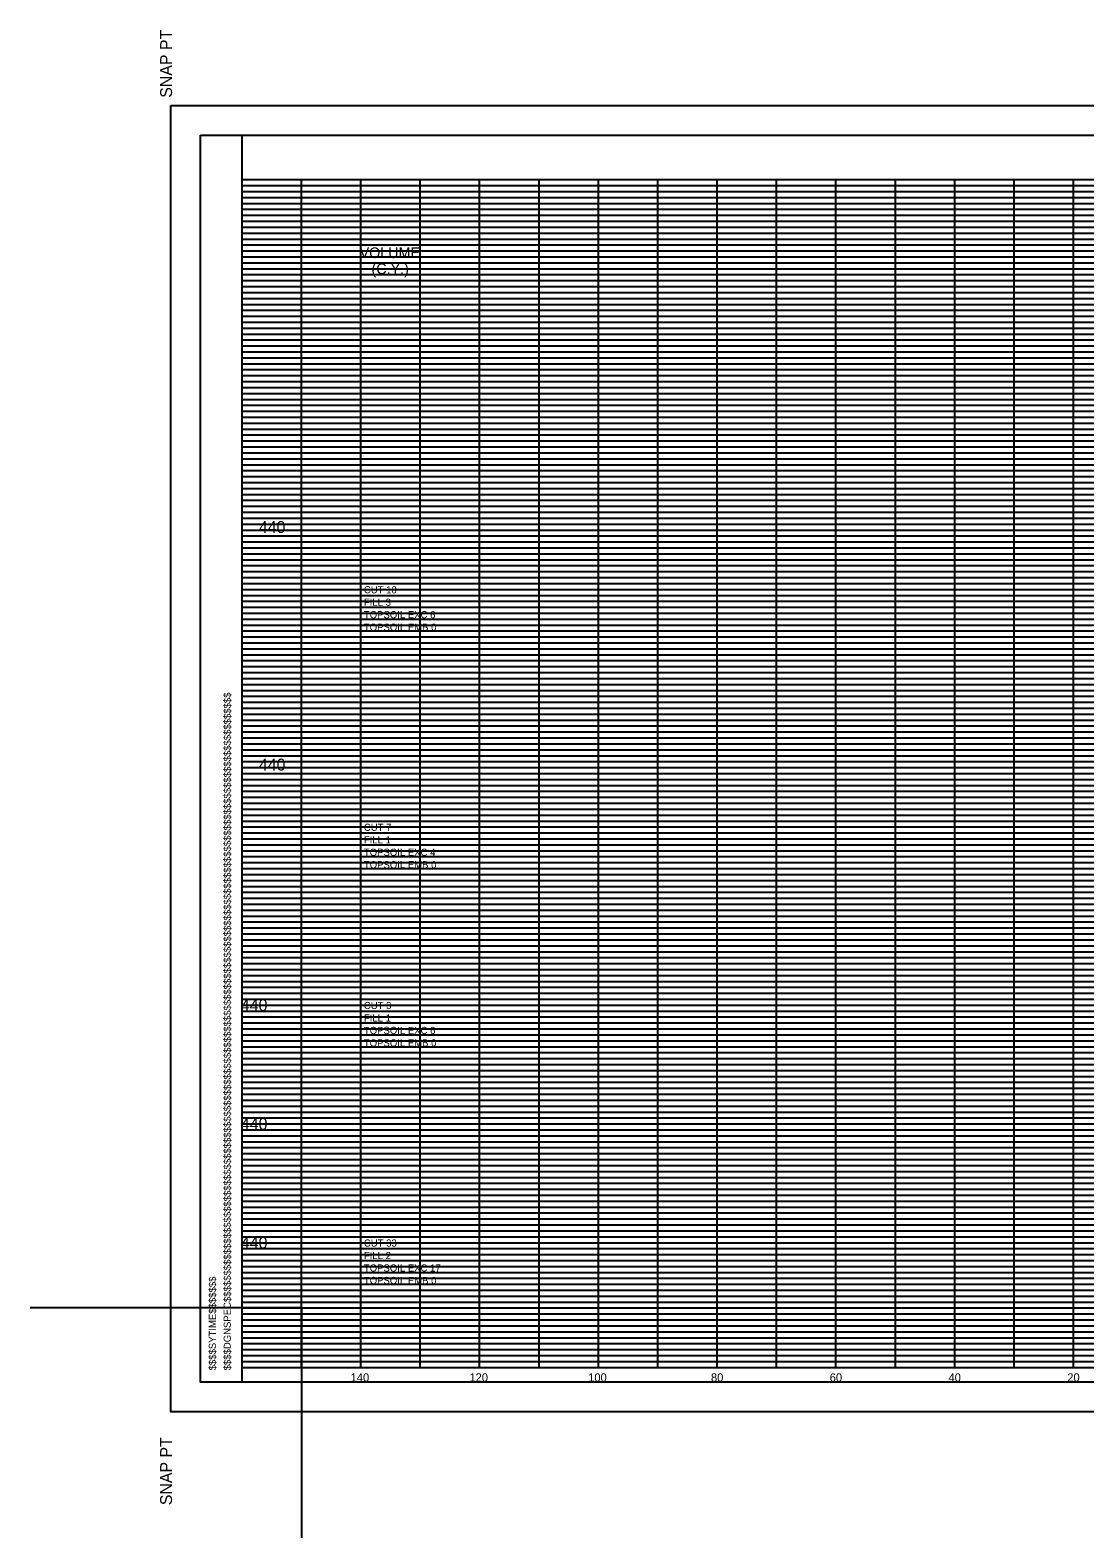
# Model space of a CAD drawing. Extents: x 37 to 1710, y 707 to 2305.
# Drawn here: x 1344.3 to 1521.9, y 1511.3 to 1765.2 of the extents above; entities that cross this region are included whole.
import ezdxf

# ---------------------------------------------------------------- set-up
doc = ezdxf.new("R2010")
doc.units = 0
for name, color, linetype in [('DESIGN - SCRATCH - User 1', 7, 'Continuous'), ('DESIGN - SHEET - Corner Text', 7, 'Continuous'), ('DESIGN - SHEET - Light Grid', 7, 'Continuous'), ('DESIGN - SHEET - Linework', 7, 'Continuous'), ('DESIGN - SHEET - Plot Shape', 7, 'Continuous'), ('DESIGN - TYPICAL - Text', 7, 'Continuous')]:
    doc.layers.add(name, color=color, linetype=linetype)

msp = doc.modelspace()

# ---------------------------------------------------------------- linework, layer by layer
at = {"layer": 'DESIGN - SCRATCH - User 1'}
for p, q in [((1390, 1550), (1344.31, 1550)), ((1390, 1550), (1390, 1511.3)), ((1380, 1540), (1380, 1540))]:
    msp.add_line(p, q, dxfattribs=at)
at = {"layer": 'DESIGN - SHEET - Light Grid'}
for p, q in [((1380, 1739), (1700, 1739)), ((1380, 1738), (1700, 1738)), ((1380, 1737), (1700, 1737)), ((1380, 1736), (1700, 1736)), ((1380, 1735), (1700, 1735)), ((1380, 1734), (1700, 1734)), ((1380, 1733), (1700, 1733)), ((1380, 1732), (1700, 1732)), ((1380, 1731), (1700, 1731)), ((1380, 1729), (1700, 1729)), ((1380, 1728), (1700, 1728)), ((1380, 1727), (1700, 1727)), ((1380, 1726), (1700, 1726)), ((1380, 1725), (1700, 1725)), ((1380, 1724), (1700, 1724)), ((1380, 1723), (1700, 1723)), ((1380, 1722), (1700, 1722)), ((1380, 1721), (1700, 1721)), ((1380, 1719), (1700, 1719)), ((1380, 1718), (1700, 1718)), ((1380, 1717), (1700, 1717)), ((1380, 1716), (1700, 1716)), ((1380, 1715), (1700, 1715)), ((1380, 1714), (1700, 1714)), ((1380, 1713), (1700, 1713)), ((1380, 1712), (1700, 1712)), ((1380, 1711), (1700, 1711)), ((1380, 1709), (1700, 1709)), ((1380, 1708), (1700, 1708)), ((1380, 1707), (1700, 1707)), ((1380, 1706), (1700, 1706)), ((1380, 1705), (1700, 1705)), ((1380, 1704), (1700, 1704)), ((1380, 1703), (1700, 1703)), ((1380, 1702), (1700, 1702)), ((1380, 1701), (1700, 1701)), ((1380, 1699), (1700, 1699)), ((1380, 1698), (1700, 1698)), ((1380, 1697), (1700, 1697)), ((1380, 1696), (1700, 1696)), ((1380, 1695), (1700, 1695)), ((1380, 1694), (1700, 1694)), ((1380, 1693), (1700, 1693)), ((1380, 1692), (1700, 1692)), ((1380, 1691), (1700, 1691)), ((1380, 1689), (1700, 1689)), ((1380, 1688), (1700, 1688)), ((1380, 1687), (1700, 1687)), ((1380, 1686), (1700, 1686)), ((1380, 1685), (1700, 1685)), ((1380, 1684), (1700, 1684)), ((1380, 1683), (1700, 1683)), ((1380, 1682), (1700, 1682)), ((1380, 1681), (1700, 1681)), ((1380, 1679), (1700, 1679)), ((1380, 1678), (1700, 1678)), ((1380, 1677), (1700, 1677)), ((1380, 1676), (1700, 1676)), ((1380, 1675), (1700, 1675)), ((1380, 1674), (1700, 1674)), ((1380, 1673), (1700, 1673)), ((1380, 1672), (1700, 1672)), ((1380, 1671), (1700, 1671)), ((1380, 1669), (1700, 1669)), ((1380, 1668), (1700, 1668)), ((1380, 1667), (1700, 1667)), ((1380, 1666), (1700, 1666)), ((1380, 1665), (1700, 1665)), ((1380, 1664), (1700, 1664)), ((1380, 1663), (1700, 1663)), ((1380, 1662), (1700, 1662)), ((1380, 1661), (1700, 1661)), ((1380, 1659), (1700, 1659)), ((1380, 1658), (1700, 1658)), ((1380, 1657), (1700, 1657)), ((1380, 1656), (1700, 1656)), ((1380, 1655), (1700, 1655)), ((1380, 1654), (1700, 1654)), ((1380, 1653), (1700, 1653)), ((1380, 1652), (1700, 1652)), ((1380, 1651), (1700, 1651)), ((1380, 1649), (1700, 1649)), ((1380, 1648), (1700, 1648)), ((1380, 1647), (1700, 1647)), ((1380, 1646), (1700, 1646)), ((1380, 1645), (1700, 1645)), ((1380, 1644), (1700, 1644)), ((1380, 1643), (1700, 1643)), ((1380, 1642), (1700, 1642)), ((1380, 1641), (1700, 1641)), ((1380, 1639), (1700, 1639)), ((1380, 1638), (1700, 1638)), ((1380, 1637), (1700, 1637)), ((1380, 1636), (1700, 1636)), ((1380, 1635), (1700, 1635)), ((1380, 1634), (1700, 1634)), ((1380, 1633), (1700, 1633)), ((1380, 1632), (1700, 1632)), ((1380, 1631), (1700, 1631)), ((1380, 1629), (1700, 1629)), ((1380, 1628), (1700, 1628)), ((1380, 1627), (1700, 1627)), ((1380, 1626), (1700, 1626)), ((1380, 1625), (1700, 1625)), ((1380, 1624), (1700, 1624)), ((1380, 1623), (1700, 1623)), ((1380, 1622), (1700, 1622)), ((1380, 1621), (1700, 1621)), ((1380, 1619), (1700, 1619)), ((1380, 1618), (1700, 1618)), ((1380, 1617), (1700, 1617)), ((1380, 1616), (1700, 1616)), ((1380, 1615), (1700, 1615)), ((1380, 1614), (1700, 1614)), ((1380, 1613), (1700, 1613)), ((1380, 1612), (1700, 1612)), ((1380, 1611), (1700, 1611)), ((1380, 1609), (1700, 1609)), ((1380, 1608), (1700, 1608)), ((1380, 1607), (1700, 1607)), ((1380, 1606), (1700, 1606)), ((1380, 1605), (1700, 1605)), ((1380, 1604), (1700, 1604)), ((1380, 1603), (1700, 1603)), ((1380, 1602), (1700, 1602)), ((1380, 1601), (1700, 1601)), ((1380, 1599), (1700, 1599)), ((1380, 1598), (1700, 1598)), ((1380, 1597), (1700, 1597)), ((1380, 1596), (1700, 1596)), ((1380, 1595), (1700, 1595)), ((1380, 1594), (1700, 1594)), ((1380, 1593), (1700, 1593)), ((1380, 1592), (1700, 1592)), ((1380, 1591), (1700, 1591)), ((1380, 1589), (1700, 1589)), ((1380, 1588), (1700, 1588)), ((1380, 1587), (1700, 1587)), ((1380, 1586), (1700, 1586)), ((1380, 1585), (1700, 1585)), ((1380, 1584), (1700, 1584)), ((1380, 1583), (1700, 1583)), ((1380, 1582), (1700, 1582)), ((1380, 1581), (1700, 1581)), ((1380, 1579), (1700, 1579)), ((1380, 1578), (1700, 1578)), ((1380, 1577), (1700, 1577)), ((1380, 1576), (1700, 1576)), ((1380, 1575), (1700, 1575)), ((1380, 1574), (1700, 1574)), ((1380, 1573), (1700, 1573)), ((1380, 1572), (1700, 1572)), ((1380, 1571), (1700, 1571)), ((1380, 1569), (1700, 1569)), ((1380, 1568), (1700, 1568)), ((1380, 1567), (1700, 1567)), ((1380, 1566), (1700, 1566)), ((1380, 1565), (1700, 1565)), ((1380, 1564), (1700, 1564)), ((1380, 1563), (1700, 1563)), ((1380, 1562), (1700, 1562)), ((1380, 1561), (1700, 1561)), ((1380, 1559), (1700, 1559)), ((1380, 1558), (1700, 1558)), ((1380, 1557), (1700, 1557)), ((1380, 1556), (1700, 1556)), ((1380, 1555), (1700, 1555)), ((1380, 1554), (1700, 1554)), ((1380, 1553), (1700, 1553)), ((1380, 1552), (1700, 1552)), ((1380, 1551), (1700, 1551)), ((1380, 1549), (1700, 1549)), ((1380, 1548), (1700, 1548)), ((1380, 1547), (1700, 1547)), ((1380, 1546), (1700, 1546)), ((1380, 1545), (1700, 1545)), ((1380, 1544), (1700, 1544)), ((1380, 1543), (1700, 1543)), ((1380, 1542), (1700, 1542)), ((1380, 1541), (1700, 1541))]:
    msp.add_line(p, q, dxfattribs=at)
at = {"layer": 'DESIGN - SHEET - Linework'}
for p, q in [((1380, 1740), (1700, 1740)), ((1390, 1540), (1390, 1740)), ((1400, 1540), (1400, 1740)), ((1410, 1540), (1410, 1740)), ((1420, 1540), (1420, 1740)), ((1430, 1540), (1430, 1740)), ((1440, 1540), (1440, 1740)), ((1450, 1540), (1450, 1740)), ((1460, 1540), (1460, 1740)), ((1470, 1540), (1470, 1740)), ((1480, 1540), (1480, 1740)), ((1490, 1540), (1490, 1740)), ((1500, 1540), (1500, 1740)), ((1510, 1540), (1510, 1740)), ((1520, 1540), (1520, 1740)), ((1380, 1730), (1700, 1730)), ((1380, 1720), (1700, 1720)), ((1380, 1710), (1700, 1710)), ((1380, 1700), (1700, 1700)), ((1380, 1690), (1700, 1690)), ((1380, 1680), (1700, 1680)), ((1380, 1670), (1700, 1670)), ((1380, 1660), (1700, 1660)), ((1380, 1650), (1700, 1650)), ((1380, 1640), (1700, 1640)), ((1380, 1630), (1700, 1630)), ((1380, 1620), (1700, 1620)), ((1380, 1610), (1700, 1610)), ((1380, 1600), (1700, 1600)), ((1380, 1590), (1700, 1590)), ((1380, 1580), (1700, 1580)), ((1380, 1570), (1700, 1570)), ((1380, 1560), (1700, 1560)), ((1380, 1550), (1700, 1550)), ((1380, 1540), (1700, 1540))]:
    msp.add_line(p, q, dxfattribs=at)
for points in [[(1368, 1752.5), (1708, 1752.5), (1708, 1532.5), (1368, 1532.5)], [(1380, 1747.5), (1700, 1747.5), (1700, 1537.5), (1380, 1537.5)]]:
    msp.add_lwpolyline(points, close=True, dxfattribs=at)
at = {"layer": 'DESIGN - SHEET - Plot Shape'}
msp.add_lwpolyline([(1373, 1747.5), (1703, 1747.5), (1703, 1537.5), (1373, 1537.5)], close=True, dxfattribs=at)

# ---------------------------------------------------------------- texts
at = {"layer": 'DESIGN - SHEET - Corner Text'}
for s, height, p in [('  SNAP PT', 2, (1368.2, 1752.3)), ('$$$$DGNSPEC$$$$$$$$$$$$$$$$$$$$$$$$$$$$$$$$$$$$$$$$$$$$$$$$$$$$$$$$$$$$$$$$$$$$$$$$$$$$$$$$$$$$$$$$$$$$$$$$$$$$$$$$$$$$$$$$$$$', 1.2, (1378.1, 1539.5)), ('$$$$SYTIME$$$$$$$', 1.2, (1375.6, 1539.5)), ('SNAP PT  ', 2, (1368.2, 1516.8))]:
    msp.add_text(s, height=height, rotation=90, dxfattribs=at).set_placement(p)
at = {"layer": 'DESIGN - TYPICAL - Text'}
for s, height, p in [('VOLUME', 1.8, (1399.79, 1726.79)), ('   (C.Y.)', 1.8, (1399.79, 1724.09)), ('440', 2, (1382.84, 1680.5)), ('CUT 10', 1.2, (1400.51, 1670.34)), ('FILL 3', 1.2, (1400.51, 1668.24)), ('TOPSOIL EXC 6', 1.2, (1400.51, 1666.14)), ('TOPSOIL EMB 0', 1.2, (1400.51, 1664.04)), ('440', 2, (1382.84, 1640.5)), ('CUT 7', 1.2, (1400.51, 1630.34)), ('TOPSOIL EXC 4', 1.2, (1400.51, 1626.14)), ('FILL 1', 1.2, (1400.51, 1628.24)), ('TOPSOIL EMB 0', 1.2, (1400.51, 1624.04)), ('     440     ', 2, (1376.09, 1600)), ('CUT 3', 1.2, (1400.51, 1600.34)), ('FILL 1', 1.2, (1400.51, 1598.24)), ('TOPSOIL EXC 6', 1.2, (1400.51, 1596.14)), ('TOPSOIL EMB 0', 1.2, (1400.51, 1594.04)), ('     440     ', 2, (1376.09, 1580)), ('     440     ', 2, (1376.09, 1560)), ('CUT 33', 1.2, (1400.51, 1560.34)), ('FILL 2', 1.2, (1400.51, 1558.24)), ('TOPSOIL EXC 17', 1.2, (1400.51, 1556.14)), ('TOPSOIL EMB 0', 1.2, (1400.51, 1554.04)), ('     140     ', 1.4, (1395.68, 1537.6)), ('     120     ', 1.4, (1415.68, 1537.6)), ('     100     ', 1.4, (1435.68, 1537.6)), ('     80     ', 1.4, (1456.35, 1537.6)), ('     60     ', 1.4, (1476.35, 1537.6)), ('     40     ', 1.4, (1496.35, 1537.6)), ('     20     ', 1.4, (1516.35, 1537.6))]:
    msp.add_text(s, height=height, dxfattribs=at).set_placement(p)

doc.saveas('drawing.dxf')
